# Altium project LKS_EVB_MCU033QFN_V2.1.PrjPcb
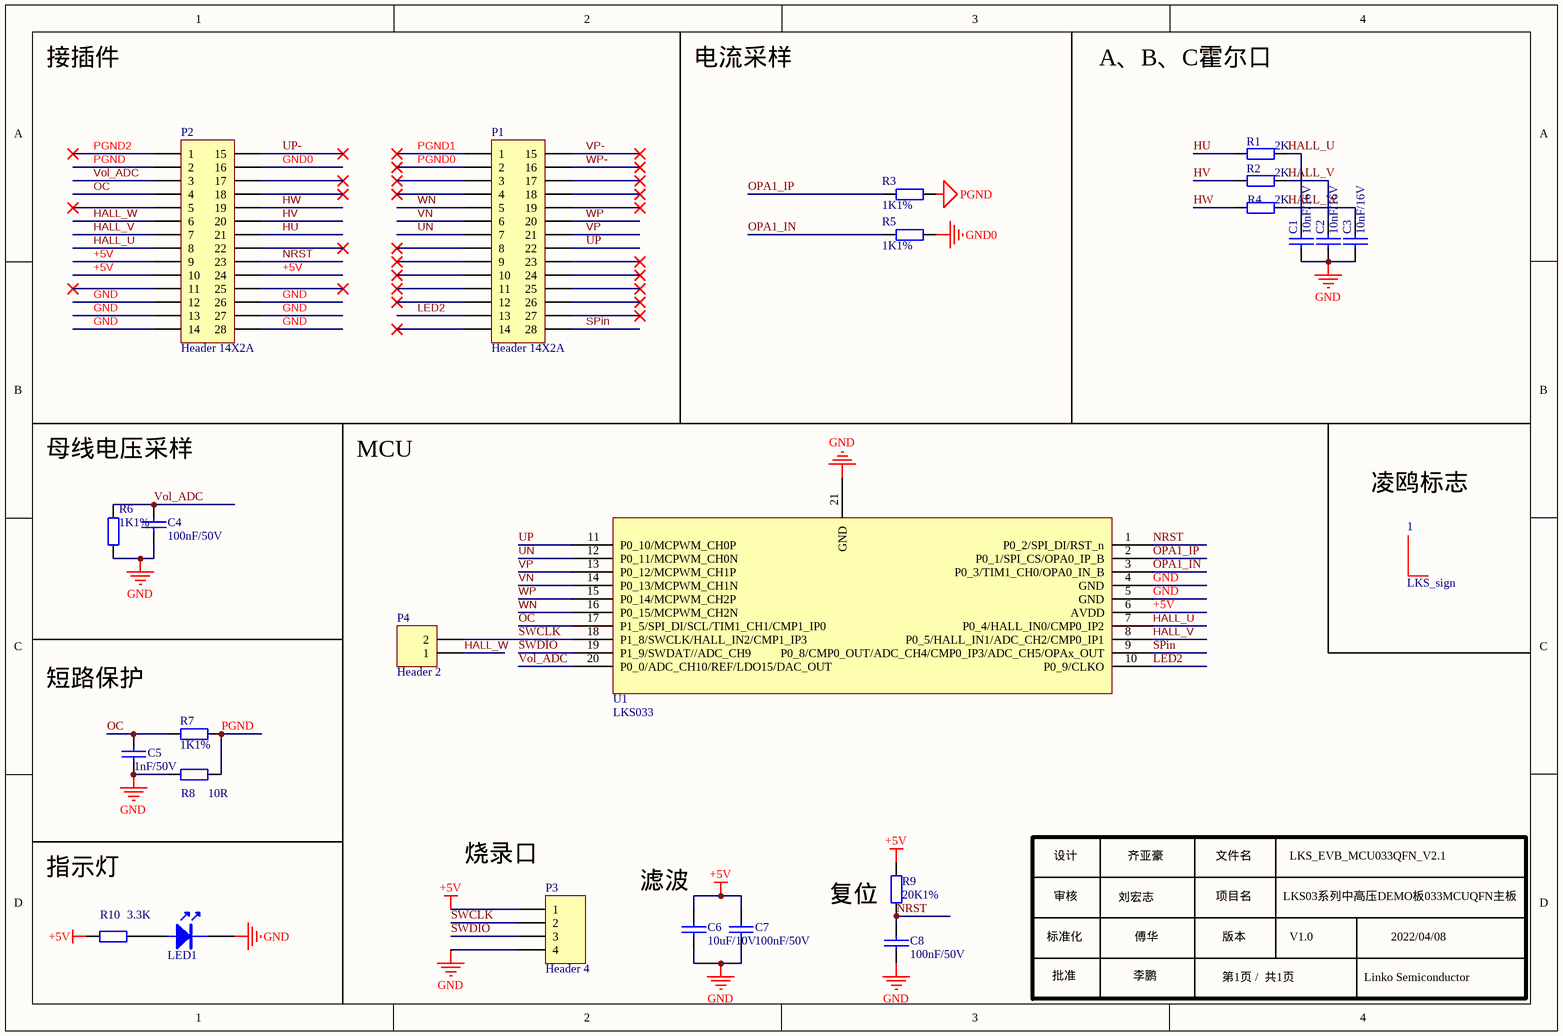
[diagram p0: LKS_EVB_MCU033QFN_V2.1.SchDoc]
1 sheet, 25 parts. Net scope: global (net labels, ports and power ports of the same name join across sheets).
Board file: LKS_EVB_MCU033QFN_V2.1.PcbDoc

## Sheet LKS_EVB_MCU033QFN_V2.1.SchDoc
size A4; SheetNumber: 1; SheetTotal: 1

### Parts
1  LKS_sign  [LKS_LOGO2]
C1  10nF/16V  [0603C]
C2  10nF/16V  [0603C]
C3  10nF/16V  [0603C]
C4  100nF/50V  [0603C]
C5  1nF/50V  [0603C]
C6  10uF/10V  [0603C]
C7  100nF/50V  [0603C]
C8  100nF/50V  [0603C]
LED1  LED  [0603D]  (value not drawn)
P1  Header 14X2A  [HDR2X14_CEN]
P2  Header 14X2A  [HDR2X14_CEN]
P3  Header 4  [HDR1X4]
P4  Header 2  [HDR1X2]
R1  2K  [0603R]
R2  2K  [0603R]
R3  1K1%  [0603R]
R4  2K  [0603R]
R5  1K1%  [0603R]
R6  1K1%  [0603R]
R7  1K1%  [0603R]
R8  10R  [0603R]
R9  20K1%  [0603R]
R10  3.3K  [0603R]
U1  LKS033  [QFN20 3x3_M]

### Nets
+5V: C6.2 C7.2 P2.9 P2.10 P2.24 P3.1 R9.1 R10.1 U1.6(AVDD)
GND: C1.2 C2.2 C3.2 C4.1 C5.1 C6.1 C7.1 C8.2 LED1.2(K) P2.12 P2.13 P2.14 P2.26 P2.27 P2.28 P3.4 R6.1 R8.2 U1.4(GND) U1.5(GND) U1.21(GND)
GND0: P2.16 R5.1
PGND: P2.2 R3.1 R7.2 R8.1
HALL_U: C1.1 P2.8 R1.2 U1.7(P0_4/HALL_IN0/CMP0_IP2)
HALL_V: C2.1 P2.7 R2.2 U1.8(P0_5/HALL_IN1/ADC_CH2/CMP0_IP1)
HALL_W: C3.1 P2.6 P4.1 R4.2
HU: P2.21 R1.1
HV: P2.20 R2.1
HW: P2.19 R4.1
LED2: P1.13 U1.10(P0_9/CLKO)
NRST: C8.1 P2.23 R9.2 U1.1(P0_2/SPI_DI/RST_n)
OC: C5.2 P2.4 R7.1 U1.17(P1_5/SPI_DI/SCL/TIM1_CH1/CMP1_IP0)
OPA1_IN: R5.2 U1.3(P0_3/TIM1_CH0/OPA0_IN_B)
OPA1_IP: R3.2 U1.2(P0_1/SPI_CS/OPA0_IP_B)
PGND0: P1.2
PGND1: P1.1
PGND2: P2.1
SPin: P1.28 U1.9(P0_8/CMP0_OUT/ADC_CH4/CMP0_IP3/ADC_CH5/OPAx_OUT)
SWCLK: P3.2 P4.2 U1.18(P1_8/SWCLK/HALL_IN2/CMP1_IP3)
SWDIO: P3.3 U1.19(P1_9/SWDAT//ADC_CH9)
UN: P1.7 U1.12(P0_11/MCPWM_CH0N)
UP: P1.22 U1.11(P0_10/MCPWM_CH0P)
UP-: P2.15
VN: P1.6 U1.14(P0_13/MCPWM_CH1N)
Vol_ADC: C4.2 P2.3 R6.2 U1.20(P0_0/ADC_CH10/REF/LDO15/DAC_OUT)
VP: P1.21 U1.13(P0_12/MCPWM_CH1P)
VP-: P1.15
WN: P1.5 U1.16(P0_15/MCPWM_CH2N)
WP: P1.20 U1.15(P0_14/MCPWM_CH2P)
WP-: P1.16
NetLED1_1: LED1.1(A) R10.2

Not connected (* = marked no-connect by the designer): P1 3* 4* 8* 9* 10* 11* 12* 14* 17* 18* 19* 23* 24* 25* 26* 27*; P2 5* 11* 17* 18* 22* 25*

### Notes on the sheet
- 接插件
- 电流采样
- A、B、C霍尔口
- 母线电压采样
- MCU
- (near 1) 凌鸥标志
- 短路保护
- 指示灯
- 烧录口
- (near C6) 滤波
- 复位
- 设计
- 审核
- 刘宏志
- 齐亚豪
- 文件名
- 项目名
- LKS03系列中高压DEMO板033MCUQFN主板
- LKS_EVB_MCU033QFN_V2.1
- 标准化
- 批准
- 李鹏
- 傅华
- 版本
- 第1页 /  共1页
- V1.0
- Linko Semiconductor
- 2022/04/08

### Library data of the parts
C1-C3 = CAP: Capacitor
C4-C8 = C: Capacitor
LED1 = LED: LED_Light
P1 P2 = Header 14X2A: Header, 14-Pin, Dual row
P3 = Header 4: Header, 4-Pin
P4 = Header 2: Header, 2-Pin
R1-R9 = Res: Resistor; Value: K
R10 = Res: Resistor; Value: 330
U1 = LKS32MC033H6S8_QFN: CHIP--QFN20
